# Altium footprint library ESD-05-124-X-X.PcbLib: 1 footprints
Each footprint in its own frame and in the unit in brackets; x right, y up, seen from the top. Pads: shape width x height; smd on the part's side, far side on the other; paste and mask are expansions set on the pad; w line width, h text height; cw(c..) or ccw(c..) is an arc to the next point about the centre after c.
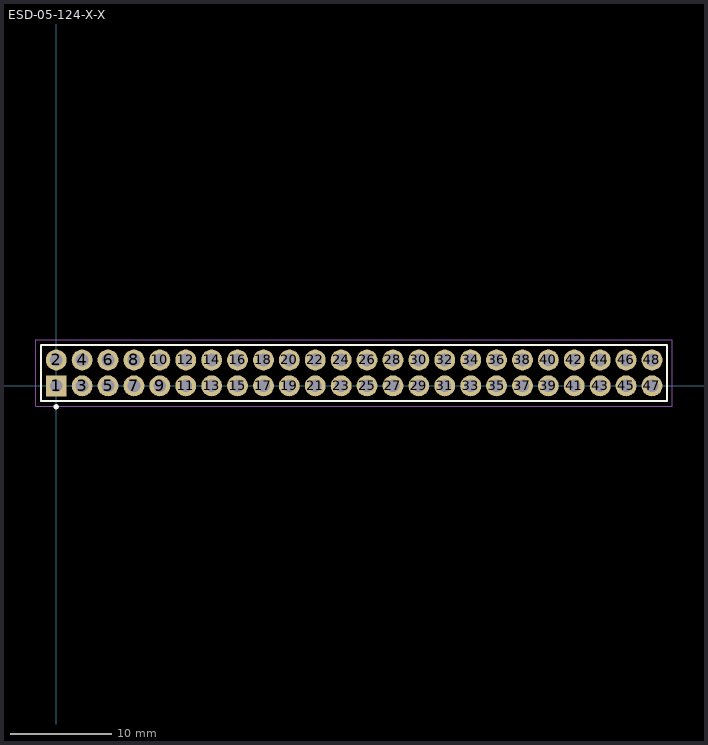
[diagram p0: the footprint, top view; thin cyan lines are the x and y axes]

## ESD-05-124-X-X [mm] "2.54mm pitch, 48 pin, socket strip; elevated, w/screw machine"
height 13.5
pads (48):
  rect 2.05x2.05 / inner round 2.05 / far side rect 2.05x2.05 hole 1.25 mask+0: 1(0,0)
  round 2.05 hole 1.25 mask+0: 2(0,2.54) 3(2.54,0) 4(2.54,2.54) 5(5.08,0) 6(5.08,2.54) 7(7.62,0) 8(7.62,2.54) 9(10.16,0) 10(10.16,2.54) 11(12.7,0) 12(12.7,2.54) 13(15.24,0) 14(15.24,2.54) 15(17.78,0) 16(17.78,2.54) 17(20.32,0) 18(20.32,2.54) 19(22.86,0) 20(22.86,2.54) 21(25.4,0) 22(25.4,2.54) 23(27.94,0) 24(27.94,2.54) 25(30.48,0) 26(30.48,2.54) 27(33.02,0) 28(33.02,2.54) 29(35.56,0) 30(35.56,2.54) 31(38.1,0) 32(38.1,2.54) 33(40.64,0) 34(40.64,2.54) 35(43.18,0) 36(43.18,2.54) 37(45.72,0) 38(45.72,2.54) 39(48.26,0) 40(48.26,2.54) 41(50.8,0) 42(50.8,2.54) 43(53.34,0) 44(53.34,2.54) 45(55.88,0) 46(55.88,2.54) 47(58.42,0) 48(58.42,2.54)
Top Overlay:
  circle w0.25: c0,-2.05 r0.125
  lines w0.2: -1.5,-1.5 59.9,-1.5 59.9,4 -1.5,4 -1.5,-1.5
Mechanical 12:
  lines w0.001: -1.5,-1.5 59.9,-1.5 59.9,4 -1.5,4 -1.5,-1.5
Mechanical 13:
  lines w0.1: -1.5,-1.5 59.9,-1.5 59.9,4 -1.5,4 -1.5,-1.5
  text ".Designator" at 0.254,0.254 h1.52
Mechanical 15:
  lines w0.05: -2,-2 60.4,-2 60.4,4.5 -2,4.5 -2,-2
